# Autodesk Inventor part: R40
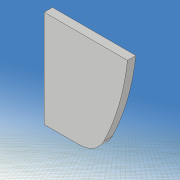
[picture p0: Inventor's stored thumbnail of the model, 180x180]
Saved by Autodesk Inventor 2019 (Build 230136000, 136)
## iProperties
Created: 2021-05
Part Number: R40
Material: 一般
Document SubType Name: Modeling
Designer: kikut
Density: 1 g/cm^3
Appearance: 既定
Mass: 0.05042 g
Surface Area: 1.90077 cm^2
Volume: 0.05042 cm^3
Author: kikut
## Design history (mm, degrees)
sketch "スケッチ1"
  geometry: L1 (80, 60)-(-80, 60); L2 (-80, 60)-(-80, -60); L3 (-80, -60)-(80, -60); L4 (80, -60)-(80, 60); L5 (80, 60)-(-80, -60); L6 (-80, 60)-(80, -60); 1 further point
  constraints: 12 end point, 2 midpoint, 2 parallel, 1 horizontal, 1 perpendicular
  dimensions: "d0" = 160 distance of L2.end L3.end; "d1" = 120 distance of L1.end L2.end
extrude "押し出し1" new body sketch "スケッチ1" stored distance "d2" = 0.6; taper "d3" = 0 deg
sketch "スケッチ2"
  geometry: L1 (-140, 0)-(140, 0) reference; L2 (0, -54)-(20, -30); L3 (0, 54)-(20, 30); L4 (0, -3)-(6.514, -3); L5 (6.514, -3)-(16, -6); L6 (16, -6)-(24, -3); L7 (24, -3)-(33.716, -3); L8 (0, 3)-(6.514, 3); L9 (6.514, 3)-(16, 6); L10 (16, 6)-(24, 3); L11 (24, 3)-(33.716, 3); L12 (0, -98)-(0, 98) reference; L13 (-100, -70)-(100, -70); L14 (100, -70)-(100, 70); L15 (100, 70)-(-100, 70); L16 (-100, 70)-(-100, -70); L17 (-100, -70)-(100, 70); L18 (100, -70)-(-100, 70); A1 r 60 centre (54.312, 28.5) between (0, 54) and (0, 3); A2 r 60 centre (54.312, -28.5) between (0, -3) and (0, -54); A3 r 18.111 centre (18, -12) between (20, -30) and (33.716, -3); A4 r 18.111 centre (18, 12) between (33.716, 3) and (20, 30); 1 further point
  constraints: 32 end point, 8 point on circle, 8 symmetric about line, 4 centre point, 3 horizontal, 2 collinear, 2 midpoint, 2 parallel, 1 perpendicular
  dimensions: "d5" = 60 radius of A1; "d6" = 6 distance of L8.start L4.start; "d7" = 108 distance of L3.start L2.start; "d8" = 0 horizontal distance of L3.start L8.start; "d9" = 60 distance of L3.end L2.end; "d10" = 0 horizontal distance of point (0, 0) L3.start; "d11" = 20 horizontal distance of L3.start L3.end; "d12" = 24 distance of A4.centre A3.centre; "d13" = 6 distance of L11.end L7.end; "d14" = 12 distance of L9.end L5.end; "d15" = 16 distance from line of L12 L5.end; "d16" = 24 distance from line of L6.end L12; "d17" = 200 distance of L14.end L15.end; "d18" = 140 distance of L15.end L13.start; "d30" = 18 distance from line of L12 A4.centre
extrude "押し出し2" cut sketch "スケッチ2" stored distance "d19" = 10; taper "d20" = 0 deg
sketch "スケッチ3"
  geometry: L1 (49.705, -17.97)-(33.948, -15.191); L2 (33.948, -15.191)-(34.295, -13.222); L3 (34.295, -13.222)-(50.052, -16); L4 (50.052, -16)-(49.705, -17.97); L5 (49.705, -17.97)-(34.295, -13.222); L6 (33.948, -15.191)-(50.052, -16); L7 (50.052, 16)-(34.295, 13.222); L8 (34.295, 13.222)-(33.948, 15.191); L9 (33.948, 15.191)-(49.705, 17.97); L10 (49.705, 17.97)-(50.052, 16); L11 (50.052, 16)-(33.948, 15.191); L12 (34.295, 13.222)-(49.705, 17.97); L13 (-112, 0)-(112, 0) reference; L14 (0, -84)-(0, 84) reference; 3 further points
  constraints: 24 end point, 4 midpoint, 4 parallel, 2 perpendicular, 2 symmetric about line
  dimensions: "d21" = 2 distance of L3.end L1.start; "d22" = 2 distance of L9.end L7.start; "d23" = 16 distance of L8.end L9.end; "d24" = 42 distance from line of L14 point (42, 15.596); "d26" = 10 deg angle of L7 L13; "d62" = 16 distance from line of L3.end L13
extrude "押し出し3" join sketch "スケッチ3" distance "d27" = 0.6; taper "d28" = 0 deg
fillet "フィレット1" dims "d31" = 2
fillet "フィレット2" dims "d32" = 1
sketch "スケッチ6"
  geometry: L1 (-20, 60)-(80, 60); L2 (80, 60)-(80, -60); L3 (80, -60)-(-20, -60); L4 (-20, -60)-(-20, 60); L5 (-46.168, 0)-(93.832, 0) reference; L6 (0, -84)-(0, 84) reference; L7 (30, 0)-(37, 0); L8 (37, 0)-(37, 10); L9 (37, 10)-(30, 10); L10 (30, 10)-(30, 0); 1 further point
  constraints: 16 end point, 4 parallel, 2 horizontal, 2 perpendicular, 1 other
  dimensions: "d63" = 120 distance of L3.end L1.start; "d64" = 100 distance of L1.start L1.end; "d65" = 20 distance between parallel lines of L6 L4; "d66" = 7 distance of L8.end L9.end; "d73" = 10 distance of L9.end L7.start; "d74" = 0 distance between parallel lines of L7 L5; "d75" = 50 distance between parallel lines of L10 L4
extrude "押し出し4" cut sketch "スケッチ6" stored distance "d70" = 10; taper "d71" = 0 deg
node "ソリッド1"
